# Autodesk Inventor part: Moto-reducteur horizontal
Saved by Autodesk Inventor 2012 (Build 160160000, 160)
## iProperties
Created: 2013-08
Part Number: Moto-reducteur horizontal
Material: Default
Document SubType Name: Modeling
Designer: hilarion
Density: 1 g/cm^3
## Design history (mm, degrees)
node "Moto-reducteur horizontal1"
node "Moto-reducteur horizontal"
node "Base1"
